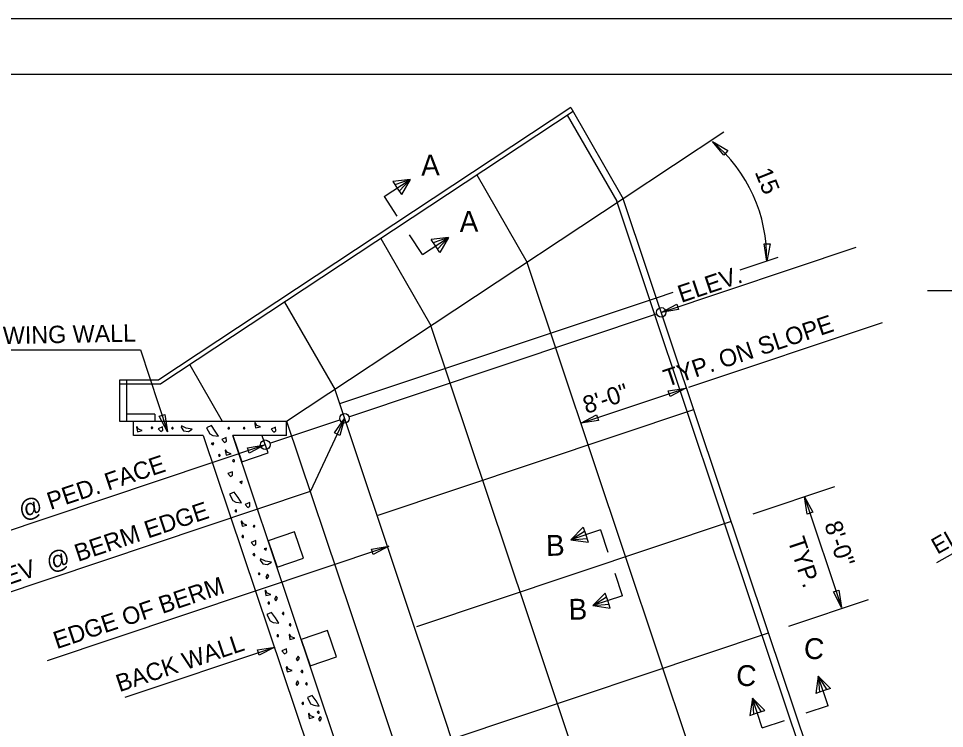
# Model space of a CAD drawing. Extents: x 0 to 272, y 0 to 188.
# Drawn here: x 94 to 160.5, y 125 to 176 of the extents above; entities that cross this region are included whole.
import ezdxf

# ---------------------------------------------------------------- set-up
doc = ezdxf.new("R2010")
doc.units = 0
for name, color, linetype in [('BORDER_ANNO_Cutsheet', 7, 'Continuous'), ('BRDG_ANNO_Anno-Sheet', 7, 'Continuous'), ('BRDG_ANNO_General-Notes', 7, 'Continuous'), ('BRDG_BASE_Hidden-Line', 7, 'Continuous'), ('BRDG_BASE_Obj-Line', 7, 'Continuous'), ('BRDG_BASE_Pattern', 7, 'Continuous')]:
    doc.layers.add(name, color=color, linetype=linetype)

msp = doc.modelspace()

# ---------------------------------------------------------------- linework, layer by layer
at = {"layer": 'BORDER_ANNO_Cutsheet'}
msp.add_lwpolyline([(0, 176), (272, 176), (272, 0), (0, 0)], close=True, dxfattribs=at)
at = {"layer": 'BRDG_ANNO_Anno-Sheet'}
msp.add_lwpolyline([(12, 172), (268, 172), (268, 4), (12, 4)], close=True, dxfattribs=at)
at = {"layer": 'BRDG_ANNO_General-Notes'}
for p, q in [((144.696, 167.817), (137.461, 163.032)), ((144.696, 166.185), (143.872, 167.148)), ((143.872, 167.148), (144.964, 166.504)), ((144.964, 166.504), (144.696, 166.185)), ((120.267, 163.194), (122.149, 164.428)), ((122.149, 164.428), (120.9, 164.282)), ((122.149, 164.428), (121.054, 164.046)), ((122.149, 164.428), (121.363, 163.576)), ((122.149, 164.428), (121.517, 163.341)), ((120.9, 164.282), (121.208, 163.811)), ((121.208, 163.811), (121.517, 163.341)), ((120.267, 163.194), (121.193, 161.783)), ((123.019, 159.028), (122.094, 160.44)), ((123.019, 159.028), (124.9, 160.262)), ((124.9, 160.262), (123.651, 160.116)), ((123.96, 159.645), (123.651, 160.116)), ((124.9, 160.262), (123.805, 159.88)), ((124.9, 160.262), (124.114, 159.41)), ((124.9, 160.262), (124.268, 159.175)), ((147.587, 159.796), (148.004, 159.787)), ((147.766, 158.542), (147.587, 159.796)), ((148.004, 159.787), (147.766, 158.542)), ((124.268, 159.175), (123.96, 159.645)), ((140.185, 154.872), (154.2, 159.561)), ((145.847, 157.929), (148.593, 158.848)), ((159.31, 156.448), (169.479, 156.448)), ((139.84, 155.919), (141.034, 156.319)), ((139.84, 155.919), (139.84, 155.919)), ((140.185, 154.872), (141.304, 155.466)), ((141.436, 155.071), (140.185, 154.872)), ((141.304, 155.466), (141.436, 155.071)), ((117.748, 147.365), (139.852, 154.76)), ((142.162, 149.494), (156.086, 154.153)), ((91.339, 152.184), (102.763, 152.184)), ((102.763, 152.184), (104.704, 146.277)), ((134.415, 146.902), (141.945, 149.421)), ((140.693, 149.222), (141.945, 149.421)), ((140.826, 148.827), (140.693, 149.222)), ((141.945, 149.421), (140.826, 148.827)), ((142.534, 147.889), (142.534, 147.889)), ((104.116, 147.399), (104.512, 147.529)), ((104.704, 146.277), (104.116, 147.399)), ((104.512, 147.529), (104.704, 146.277)), ((112.057, 145.46), (117.095, 147.146)), ((117.431, 147.249), (114.983, 142.005)), ((116.714, 146.204), (117.431, 147.249)), ((117.431, 147.249), (117.091, 146.028)), ((134.415, 146.902), (135.535, 147.496)), ((135.667, 147.101), (134.415, 146.902)), ((135.535, 147.496), (135.667, 147.101)), ((159.984, 136.874), (178.851, 147.549)), ((117.091, 146.028), (116.714, 146.204)), ((88.352, 137.529), (111.7, 145.341)), ((110.448, 145.142), (111.7, 145.341)), ((110.58, 144.747), (110.448, 145.142)), ((111.7, 145.341), (110.58, 144.747)), ((90.304, 133.747), (114.983, 142.005)), ((146.801, 140.385), (152.673, 142.349)), ((150.485, 141.617), (153.152, 133.646)), ((150.684, 140.366), (150.485, 141.617)), ((150.485, 141.617), (151.079, 140.498)), ((151.079, 140.498), (150.684, 140.366)), ((145.228, 139.858), (145.228, 139.858)), ((133.693, 138.527), (134.585, 139.414)), ((135.829, 139.233), (133.693, 138.527)), ((133.693, 138.527), (134.673, 139.147)), ((134.585, 139.414), (134.761, 138.88)), ((135.829, 139.233), (136.36, 137.631)), ((133.693, 138.527), (134.85, 138.613)), ((133.693, 138.527), (134.938, 138.346)), ((134.761, 138.88), (134.938, 138.346)), ((96.075, 129.838), (120.613, 138.049)), ((119.362, 137.85), (120.613, 138.049)), ((119.494, 137.454), (119.362, 137.85)), ((120.613, 138.049), (119.494, 137.454)), ((137.414, 134.499), (136.884, 136.101)), ((135.277, 133.792), (136.169, 134.679)), ((137.414, 134.499), (135.277, 133.792)), ((136.345, 134.145), (136.169, 134.679)), ((152.558, 134.766), (152.953, 134.898)), ((153.152, 133.646), (152.558, 134.766)), ((152.953, 134.898), (153.152, 133.646)), ((135.277, 133.792), (136.257, 134.412)), ((135.277, 133.792), (136.434, 133.878)), ((135.277, 133.792), (136.522, 133.611)), ((136.522, 133.611), (136.345, 134.145)), ((149.361, 132.31), (155.08, 134.223)), ((147.921, 131.828), (147.921, 131.828)), ((101.661, 127.211), (112.414, 130.809)), ((111.163, 130.61), (112.414, 130.809)), ((111.295, 130.215), (111.163, 130.61)), ((112.414, 130.809), (111.295, 130.215)), ((151.471, 128.716), (151.29, 127.472)), ((152.177, 126.58), (151.471, 128.716)), ((151.471, 128.716), (152.358, 127.825)), ((151.471, 128.716), (151.557, 127.56)), ((151.471, 128.716), (152.091, 127.737)), ((152.358, 127.825), (151.824, 127.648)), ((146.736, 127.132), (146.556, 125.888)), ((147.443, 124.996), (146.736, 127.132)), ((146.736, 127.132), (147.624, 126.241)), ((146.736, 127.132), (147.357, 126.152)), ((146.736, 127.132), (146.823, 125.976)), ((151.824, 127.648), (151.29, 127.472)), ((152.177, 126.58), (150.575, 126.05)), ((146.556, 125.888), (147.09, 126.064)), ((147.09, 126.064), (147.624, 126.241)), ((147.443, 124.996), (149.045, 125.526))]:
    msp.add_line(p, q, dxfattribs=at)
for centre in [(140.186, 154.869), (117.428, 147.251), (111.734, 145.352)]:
    msp.add_circle(centre, 0.343, dxfattribs=at)
msp.add_arc((136.875, 158.797), 10.894, 358.65678, 50.03979, dxfattribs=at)
at = {"layer": 'BRDG_BASE_Hidden-Line'}
for p, q in [((133.438, 169.049), (136.987, 162.873)), ((146.871, 133.332), (136.987, 162.873)), ((101.77, 150.026), (101.77, 147.026)), ((103.789, 147.54), (101.789, 147.54)), ((103.789, 147.54), (103.789, 147.04)), ((117.894, 133.268), (113.287, 147.035)), ((127.627, 104.179), (117.894, 133.268)), ((153.887, 112.363), (146.871, 133.332))]:
    msp.add_line(p, q, dxfattribs=at)
at = {"layer": 'BRDG_BASE_Obj-Line'}
for p, q in [((133.682, 169.609), (104.072, 150.026)), ((133.848, 169.319), (104.234, 149.733)), ((133.682, 169.609), (137.461, 163.032)), ((126.939, 164.751), (130.556, 158.456)), ((137.461, 163.032), (113.259, 147.026)), ((147.903, 131.822), (137.461, 163.032)), ((120.042, 160.183), (123.634, 153.932)), ((137.629, 137.316), (130.556, 158.456)), ((117.097, 148.31), (139.84, 155.919)), ((113.122, 155.613), (116.745, 149.308)), ((130.545, 133.277), (123.634, 153.932)), ((106.304, 151.102), (108.629, 147.055)), ((101.27, 147.026), (101.27, 150.026)), ((101.27, 150.026), (104.072, 150.026)), ((101.27, 149.733), (104.234, 149.733)), ((122.084, 133.352), (116.745, 149.308)), ((119.854, 140.3), (142.534, 147.889)), ((113.259, 147.026), (101.27, 147.026)), ((102.27, 146.026), (102.27, 147.026)), ((113.259, 146.026), (113.259, 147.026)), ((107.272, 146.026), (102.27, 146.026)), ((107.272, 146.026), (122.812, 99.749)), ((113.259, 146.026), (109.394, 146.026)), ((109.394, 146.026), (110.036, 144.131)), ((113.648, 133.351), (109.406, 146.029)), ((111.93, 144.772), (111.514, 146.001)), ((110.036, 144.131), (111.93, 144.772)), ((122.621, 132.294), (145.228, 139.858)), ((113.838, 139.084), (111.944, 138.443)), ((114.479, 137.189), (113.838, 139.084)), ((111.944, 138.443), (112.585, 136.548)), ((112.585, 136.548), (114.479, 137.189)), ((146.725, 110.131), (137.629, 137.316)), ((124.892, 99.747), (113.648, 133.351)), ((123.466, 129.22), (122.084, 133.352)), ((139.086, 107.75), (130.545, 133.277)), ((116.211, 131.994), (114.317, 131.353)), ((116.852, 130.1), (116.211, 131.994)), ((125.314, 124.264), (147.903, 131.822)), ((154.364, 112.512), (147.903, 131.822)), ((114.317, 131.353), (114.958, 129.459)), ((114.958, 129.459), (116.852, 130.1)), ((133.647, 98.749), (123.453, 129.216))]:
    msp.add_line(p, q, dxfattribs=at)
at = {"layer": 'BRDG_BASE_Pattern'}
for points in [[(102.472, 146.617), (102.538, 146.289), (102.89, 146.378), (102.632, 146.476), (102.501, 146.673)], [(103.522, 146.603), (103.551, 146.528), (103.607, 146.528), (103.64, 146.561), (103.64, 146.59), (103.612, 146.618), (103.593, 146.627), (103.564, 146.627)], [(104.031, 146.507), (104.222, 146.297), (104.372, 146.391), (104.354, 146.644)], [(105.004, 146.57), (105.032, 146.494), (105.088, 146.494), (105.121, 146.528), (105.121, 146.556), (105.093, 146.584), (105.074, 146.593), (105.045, 146.593)], [(105.687, 146.613), (105.856, 146.36), (106.203, 146.295), (106.485, 146.482), (106.048, 146.544), (105.711, 146.72)], [(107.519, 146.579), (107.745, 146.127), (107.97, 146.015), (108.364, 145.959), (108.139, 146.334), (107.858, 146.728)], [(109.044, 146.57), (109.072, 146.494), (109.128, 146.494), (109.161, 146.528), (109.161, 146.556), (109.133, 146.584), (109.114, 146.593), (109.085, 146.593)], [(110.155, 146.57), (110.183, 146.494), (110.239, 146.494), (110.272, 146.528), (110.272, 146.556), (110.244, 146.584), (110.225, 146.593), (110.196, 146.593)], [(110.972, 146.887), (111.038, 146.559), (111.39, 146.648), (111.132, 146.747), (111.001, 146.943)], [(112.145, 146.474), (112.336, 146.263), (112.486, 146.357), (112.468, 146.61)], [(108.61, 145.733), (108.801, 145.523), (108.951, 145.617), (108.933, 145.869)], [(107.84, 145.448), (107.99, 145.336), (108.028, 145.487)], [(108.37, 144.617), (108.399, 144.542), (108.455, 144.542), (108.488, 144.575), (108.488, 144.604), (108.46, 144.632), (108.441, 144.64), (108.412, 144.64)], [(108.851, 144.934), (108.917, 144.607), (109.269, 144.695), (109.011, 144.794), (108.88, 144.991)], [(109.387, 144.203), (109.457, 144.132), (109.513, 144.141), (109.513, 144.16), (109.513, 144.216), (109.494, 144.272), (109.462, 144.277), (109.433, 144.267), (109.424, 144.259), (109.411, 144.235)], [(109.047, 143.275), (109.239, 143.065), (109.388, 143.159), (109.371, 143.412)], [(109.893, 142.688), (110.043, 142.575), (110.081, 142.726)], [(109.169, 141.798), (109.395, 141.346), (109.62, 141.234), (110.014, 141.178), (109.789, 141.553), (109.507, 141.948)], [(110.293, 141.053), (110.484, 140.843), (110.634, 140.937), (110.616, 141.19)], [(109.543, 140.594), (109.614, 140.523), (109.67, 140.532), (109.67, 140.551), (109.67, 140.607), (109.651, 140.664), (109.618, 140.668), (109.59, 140.658), (109.581, 140.65), (109.568, 140.626)], [(109.996, 139.817), (110.062, 139.489), (110.414, 139.578), (110.156, 139.676), (110.025, 139.873)], [(110.862, 139.533), (110.89, 139.458), (110.946, 139.458), (110.979, 139.491), (110.979, 139.52), (110.951, 139.548), (110.932, 139.557), (110.903, 139.557)], [(110.037, 138.756), (110.107, 138.685), (110.163, 138.694), (110.163, 138.713), (110.163, 138.769), (110.144, 138.826), (110.112, 138.83), (110.083, 138.82), (110.074, 138.812), (110.061, 138.788)], [(110.718, 138.328), (110.91, 138.118), (111.059, 138.212), (111.042, 138.464)], [(111.644, 137.873), (111.794, 137.761), (111.832, 137.912)], [(110.847, 137.45), (110.917, 137.38), (110.973, 137.388), (110.973, 137.407), (110.973, 137.463), (110.954, 137.52), (110.922, 137.524), (110.894, 137.515), (110.884, 137.506), (110.871, 137.482)], [(111.376, 137.052), (111.546, 136.798), (111.893, 136.733), (112.174, 136.92), (111.738, 136.982), (111.4, 137.159)], [(111.232, 136.099), (111.261, 136.024), (111.317, 136.024), (111.349, 136.057), (111.349, 136.086), (111.321, 136.114), (111.303, 136.123), (111.274, 136.123)], [(111.762, 135.837), (111.856, 135.706), (111.968, 135.856), (111.987, 135.912), (111.894, 136.043)], [(111.716, 134.832), (111.782, 134.504), (112.134, 134.593), (111.876, 134.691), (111.745, 134.888)], [(112.387, 134.252), (112.481, 134.121), (112.593, 134.271), (112.612, 134.328), (112.519, 134.458)], [(111.908, 133.97), (111.979, 133.9), (112.035, 133.908), (112.035, 133.927), (112.035, 133.983), (112.015, 134.04), (111.983, 134.044), (111.955, 134.035), (111.945, 134.026), (111.932, 134.002)], [(111.852, 133.145), (112.077, 132.693), (112.303, 132.581), (112.696, 132.525), (112.471, 132.9), (112.19, 133.295)], [(112.951, 133.219), (113.021, 133.149), (113.077, 133.157), (113.077, 133.176), (113.077, 133.233), (113.058, 133.289), (113.025, 133.293), (112.997, 133.284), (112.988, 133.275), (112.975, 133.252)], [(113.439, 132.4), (113.51, 132.33), (113.566, 132.338), (113.566, 132.357), (113.566, 132.413), (113.546, 132.47), (113.514, 132.474), (113.486, 132.465), (113.476, 132.456), (113.463, 132.432)], [(112.555, 131.617), (112.625, 131.546), (112.681, 131.555), (112.681, 131.574), (112.681, 131.63), (112.662, 131.686), (112.63, 131.691), (112.602, 131.681), (112.592, 131.673), (112.579, 131.649)], [(113.442, 131.679), (113.508, 131.351), (113.86, 131.44), (113.602, 131.538), (113.471, 131.735)], [(112.932, 130.532), (113.123, 130.322), (113.273, 130.416), (113.255, 130.669)], [(113.957, 129.937), (114.05, 129.806), (114.162, 129.957), (114.181, 130.013), (114.088, 130.144)], [(113.241, 129.347), (113.306, 129.02), (113.658, 129.108), (113.4, 129.207), (113.27, 129.404)], [(114.295, 129.05), (114.366, 128.98), (114.422, 128.988), (114.422, 129.007), (114.422, 129.063), (114.402, 129.12), (114.37, 129.124), (114.342, 129.115), (114.333, 129.106), (114.32, 129.082)], [(113.923, 128.166), (114.017, 128.036), (114.129, 128.186), (114.148, 128.242), (114.055, 128.373)], [(114.62, 128.153), (114.691, 128.083), (114.747, 128.091), (114.747, 128.111), (114.747, 128.167), (114.727, 128.223), (114.695, 128.228), (114.667, 128.218), (114.658, 128.21), (114.645, 128.186)], [(114.766, 127.183), (114.991, 126.731), (115.217, 126.619), (115.61, 126.563), (115.385, 126.938), (115.104, 127.333)], [(114.363, 126.752), (114.433, 126.682), (114.489, 126.691), (114.489, 126.71), (114.489, 126.766), (114.47, 126.822), (114.438, 126.827), (114.409, 126.817), (114.4, 126.809), (114.387, 126.785)], [(114.832, 125.996), (114.898, 125.669), (115.25, 125.757), (114.992, 125.856), (114.861, 126.053)], [(115.472, 126.114), (115.543, 126.043), (115.599, 126.052), (115.599, 126.071), (115.599, 126.127), (115.579, 126.183), (115.547, 126.188), (115.519, 126.178), (115.509, 126.17), (115.496, 126.146)], [(115.548, 125.611), (115.642, 125.48), (115.754, 125.63), (115.773, 125.687), (115.68, 125.817)]]:
    msp.add_lwpolyline(points, close=True, dxfattribs=at)

# ---------------------------------------------------------------- texts
at = {"layer": 'BRDG_ANNO_General-Notes'}
for s, height, rotation, p in [('A', 1.5, 1.1, (122.941, 164.692)), ('15', 1.25, 291.80147, (146.892, 164.962)), ('A', 1.5, 1.1, (125.708, 160.653)), ('ELEV.', 1.25, 18.49994, (141.627, 155.55)), ('  8\'-0"      TYP. ON SLOPE', 1.25, 18.49992, (133.929, 147.266)), ('WING WALL', 1.25, 1.1, (92.89, 152.586)), ('@ PED. FACE', 1.25, 18.49992, (94.248, 139.974)), ('@ BERM EDGE', 1.25, 18.49992, (96.225, 136.237)), ('ELEV.', 1.1818, 29.51768, (160.031, 137.441)), ('8\'-0"', 1.25, 288.50006, (151.893, 139.626)), ('B', 1.5, 1.1, (131.921, 137.356)), ('TYP.', 1.25, 288.50006, (149.256, 138.484)), ('ELEV  ', 1.25, 18.49992, (91.289, 134.595)), ('EDGE OF BERM', 1.25, 18.49991, (96.752, 130.647)), ('B', 1.5, 1.1, (133.544, 132.765)), ('BACK WALL', 1.25, 18.49994, (101.255, 127.555)), ('C', 1.5, 356.1, (150.398, 129.997)), ('C', 1.5, 356.1, (145.527, 128.057))]:
    msp.add_text(s, height=height, rotation=rotation, dxfattribs=at).set_placement(p)

doc.saveas('drawing.dxf')
